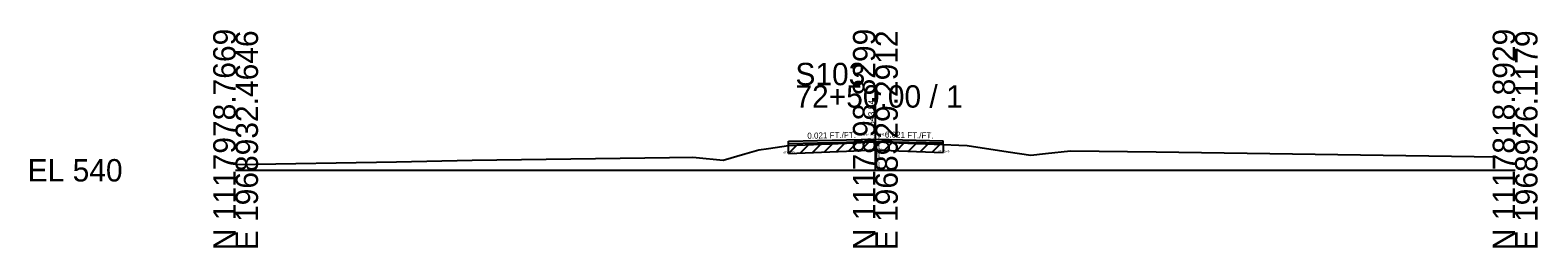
# Model space of a CAD drawing. Extents: x -26 to 163, y -10 to 24018.
# Drawn here: x -25.7 to 162.8, y 20490.3 to 20517.5 of the extents above; entities that cross this region are included whole.
import ezdxf

# ---------------------------------------------------------------- set-up
doc = ezdxf.new("R2010")
doc.units = 0
for name, color, linetype in [('RD_GPK_XS_Cell', 7, 'Continuous'), ('RD_XS_ExGround', 7, 'Continuous'), ('RD_XS_ExPaveRet', 7, 'Continuous'), ('RD_XS_Misc_Line', 7, 'Continuous'), ('RD_XS_PaveOvlay_CP', 7, 'Continuous'), ('RD_XS_TX_Elev_EX', 7, 'Continuous'), ('RD_XS_TX_ExEOP', 7, 'Continuous'), ('RD_XS_TX_Notes', 7, 'Continuous'), ('RD_XS_TX_Profile', 7, 'Continuous'), ('RD_XS_TX_Slope', 7, 'Continuous')]:
    doc.layers.add(name, color=color, linetype=linetype)

msp = doc.modelspace()

# ---------------------------------------------------------------- linework, layer by layer
at = {"layer": 'RD_GPK_XS_Cell'}
for p, q in [((80, 20500), (80, 20510.63)), ((0, 20500), (80, 20500)), ((80, 20500), (160, 20500))]:
    msp.add_line(p, q, dxfattribs=at)
at = {"layer": 'RD_XS_ExGround'}
msp.add_lwpolyline([(0, 20500.73), (20.11, 20501.05), (29.58, 20501.27), (54.25, 20501.61), (57.15, 20501.64), (57.57, 20501.61), (60.95, 20501.26), (63.66, 20502.04), (65.42, 20502.54), (66.62, 20502.72), (69.13, 20503.11), (76.38, 20503.4), (80.08, 20503.54), (82.92, 20503.44), (88.47, 20503.24), (90.43, 20503.15), (91.49, 20503.1), (96.62, 20502.31), (99.43, 20501.87), (101.26, 20502.09), (104.41, 20502.45), (115.13, 20502.31), (157.72, 20501.67)], dxfattribs=at)
at = {"layer": 'RD_XS_ExPaveRet'}
for p, q in [((69.13, 20502.11), (70.17, 20503.15)), ((69.13, 20502.11), (69.13, 20503.11)), ((70.63, 20502.17), (71.67, 20503.21)), ((72.13, 20502.23), (73.17, 20503.27)), ((73.63, 20502.29), (74.67, 20503.33)), ((75.13, 20502.35), (76.17, 20503.39)), ((76.63, 20502.41), (77.67, 20503.45)), ((78.13, 20502.47), (79.17, 20503.51)), ((79.63, 20502.53), (80.62, 20503.52)), ((81.13, 20502.51), (82.09, 20503.47)), ((82.63, 20502.45), (83.59, 20503.42)), ((84.13, 20502.4), (85.09, 20503.36)), ((85.63, 20502.34), (86.59, 20503.31)), ((87.13, 20502.29), (88.09, 20503.26)), ((88.47, 20503.24), (88.47, 20502.24)), ((69.13, 20502.11), (76.38, 20502.4)), ((76.38, 20502.4), (80.08, 20502.54)), ((80.08, 20502.54), (82.92, 20502.44)), ((82.92, 20502.44), (88.47, 20502.24))]:
    msp.add_line(p, q, dxfattribs=at)
at = {"layer": 'RD_XS_Misc_Line'}
msp.add_line((80.08, 20503.54), (80.08, 20500.54), dxfattribs=at)
at = {"layer": 'RD_XS_PaveOvlay_CP'}
for p, q in [((69.13, 20503.64), (80, 20503.87)), ((69.13, 20503.11), (69.13, 20503.64)), ((80, 20503.54), (69.13, 20503.32)), ((80, 20503.87), (88.47, 20503.69)), ((88.47, 20503.37), (80, 20503.54)), ((88.47, 20503.24), (88.47, 20503.69))]:
    msp.add_line(p, q, dxfattribs=at)

# ---------------------------------------------------------------- texts
at = {"layer": 'RD_GPK_XS_Cell'}
for s, p in [('N 1117978.7669', (0, 20490)), ('E 1968932.4646', (2.8, 20490)), ('N 1117898.8299', (80, 20490)), ('E 1968929.2912', (82.8, 20490)), ('N 1117818.8929', (160, 20490)), ('E 1968926.1179', (162.8, 20490))]:
    msp.add_text(s, height=2.8, rotation=90, dxfattribs=at).set_placement(p)
for s, p in [('S103', (70, 20510.63)), ('72+50.00 / 1', (70, 20507.83)), ('EL 540', (-26, 20498.6))]:
    msp.add_text(s, height=2.8, dxfattribs=at).set_placement(p)
at = {"layer": 'RD_XS_TX_Elev_EX'}
msp.add_text('543.54', height=0.8, rotation=90, dxfattribs=at).set_placement((79.9, 20505.54))
at = {"layer": 'RD_XS_TX_ExEOP'}
for s, p in [('EOP-L', (69.08, 20503.64)), ('EOP-R', (88.42, 20503.69))]:
    msp.add_text(s, height=0.1, rotation=270, dxfattribs=at).set_placement(p)
at = {"layer": 'RD_XS_TX_Notes'}
for s, p in [('Elev. @CL = 543.87', (78.48, 20504.37)), (' dE= 0.53', (68.42, 20502.11)), (' dE= 0.32', (79.29, 20502.54)), (' dE= 0.45', (87.76, 20502.24))]:
    msp.add_text(s, height=0.25, dxfattribs=at).set_placement(p)
msp.add_text(' Min. Distance @CP = -0.00', height=0.25, rotation=270, dxfattribs=at).set_placement((80.33, 20504.64))
at = {"layer": 'RD_XS_TX_Profile'}
msp.add_text('CL', height=0.25, dxfattribs=at).set_placement((79.77, 20503.87))
at = {"layer": 'RD_XS_TX_Slope'}
for rotation, p in [(1.1916, (71.5, 20503.94)), (358.8084, (81.19, 20504.09))]:
    msp.add_text('0.021 FT./FT.', height=0.75, rotation=rotation, dxfattribs=at).set_placement(p)

doc.saveas('drawing.dxf')
